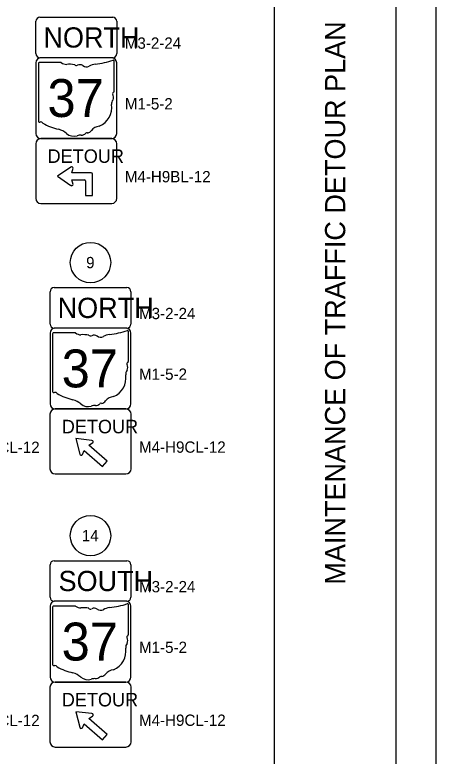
# Model space of a CAD drawing. Extents: x 0 to 680, y 0 to 440.
# Drawn here: x 575.8 to 680, y 150.5 to 333.9 of the extents above; entities that cross this region are included whole.
import ezdxf

# ---------------------------------------------------------------- set-up
doc = ezdxf.new("R2010")
doc.units = 0
for name, color, linetype in [('SH_Border', 7, 'Continuous'), ('SH_Cut_Line', 7, 'Continuous'), ('SH_Data', 7, 'Continuous'), ('SN_P_Signs', 7, 'Continuous'), ('SN_P_Text', 7, 'Continuous')]:
    doc.layers.add(name, color=color, linetype=linetype)

msp = doc.modelspace()

# ---------------------------------------------------------------- linework, layer by layer
at = {"layer": 'SH_Border'}
msp.add_line((640, 10), (640, 430), dxfattribs=at)
msp.add_lwpolyline([(30, 430), (670, 430), (670, 10), (30, 10)], close=True, dxfattribs=at)
at = {"layer": 'SH_Cut_Line'}
msp.add_lwpolyline([(0, 0), (680, 0), (680, 440), (0, 440)], close=True, dxfattribs=at)
at = {"layer": 'SN_P_Signs'}
for p, q in [((580.97, 324.26), (580.97, 332.26)), ((581.97, 333.26), (599.97, 333.26)), ((600.97, 332.26), (600.97, 324.26)), ((599.97, 323.26), (581.97, 323.26)), ((581.58, 321.81), (581.58, 307.58)), ((587.26, 322.06), (581.77, 322.06)), ((600.33, 314.97), (600.33, 322.41)), ((600.33, 314.97), (600.33, 314.97)), ((589.61, 296.18), (586.33, 293.93)), ((589.85, 294.81), (590.18, 295.94)), ((586.33, 293.93), (589.61, 291.69)), ((594.61, 294.81), (589.85, 294.81)), ((594.61, 294.81), (594.61, 294.81)), ((594.99, 289.17), (594.99, 294.44)), ((590.18, 291.93), (589.85, 293.06)), ((589.85, 293.06), (592.98, 293.06)), ((593.23, 292.81), (593.23, 289.17)), ((593.23, 289.17), (594.99, 289.17)), ((585.49, 266.39), (603.49, 266.39)), ((584.49, 257.39), (584.49, 265.39)), ((604.49, 265.39), (604.49, 257.39)), ((585.1, 254.95), (585.1, 240.72)), ((590.77, 255.2), (585.28, 255.2)), ((603.49, 256.39), (585.49, 256.39)), ((603.85, 248.11), (603.85, 255.55)), ((603.84, 248.11), (603.85, 248.11)), ((594.85, 228.61), (590.85, 229.08)), ((590.85, 229.08), (591.83, 225.23)), ((594.07, 227.42), (594.99, 227.99)), ((598.58, 223.47), (594.07, 227.42)), ((594.85, 228.61), (594.85, 228.61)), ((592.47, 225.12), (592.91, 226.1)), ((592.91, 226.1), (597.42, 222.15)), ((597.42, 222.15), (598.58, 223.47)), ((585.49, 198.86), (603.49, 198.86)), ((584.49, 189.86), (584.49, 197.86)), ((604.49, 197.86), (604.49, 189.86)), ((603.49, 188.86), (585.49, 188.86)), ((585.1, 187.41), (585.1, 173.18)), ((590.77, 187.66), (585.28, 187.66)), ((603.85, 180.57), (603.85, 188.01)), ((603.84, 180.57), (603.85, 180.57)), ((594.85, 161.07), (590.85, 161.54)), ((590.85, 161.54), (591.83, 157.7)), ((594.07, 159.89), (594.99, 160.45)), ((598.58, 155.93), (594.07, 159.89)), ((594.85, 161.07), (594.85, 161.07)), ((592.47, 157.58), (592.91, 158.56)), ((592.91, 158.57), (597.42, 154.61)), ((597.42, 154.61), (598.58, 155.93))]:
    msp.add_line(p, q, dxfattribs=at)
for points in [[(599.72, 323.26), (582.22, 323.26)], [(580.97, 322.01), (580.97, 304.51)], [(600.97, 304.51), (600.97, 322.01)], [(582.22, 303.26), (599.72, 303.26)], [(599.72, 303.26), (582.22, 303.26)], [(580.94, 301.97), (580.94, 288.48)], [(601.01, 288.48), (601.01, 301.97)], [(582.22, 287.2), (599.72, 287.2)], [(584.49, 255.14), (584.49, 237.64)], [(603.24, 256.39), (585.74, 256.39)], [(604.49, 237.64), (604.49, 255.14)], [(584.45, 235.11), (584.45, 221.62)], [(585.74, 236.39), (603.24, 236.39)], [(603.24, 236.39), (585.74, 236.39)], [(604.52, 221.62), (604.52, 235.11)], [(585.74, 220.34), (603.24, 220.34)], [(603.24, 188.86), (585.74, 188.86)], [(584.49, 187.61), (584.49, 170.11)], [(604.49, 170.11), (604.49, 187.61)], [(585.74, 168.86), (603.24, 168.86)], [(603.24, 168.86), (585.74, 168.86)], [(584.45, 167.57), (584.45, 154.08)], [(604.52, 154.08), (604.52, 167.57)], [(585.74, 152.8), (603.24, 152.8)]]:
    msp.add_lwpolyline(points, dxfattribs=at)
for centre in [(594.49, 272.59), (594.49, 205.06)]:
    msp.add_circle(centre, 5, dxfattribs=at)
for centre, radius, start, end in [((581.97, 332.26), 1, 90, 180), ((599.97, 332.26), 1, 0, 90), ((581.97, 324.26), 1, 180, 270), ((582.22, 322.01), 1.25, 90, 180), ((593.65, 341.46), 19.88, 275.8445, 288.9065), ((599.72, 322.01), 1.25, 0, 90), ((599.97, 324.26), 1, 270, 0), ((600.12, 322.44), 0.209, 351.8621, 97.738), ((581.8, 321.84), 0.217, 98.1301, 188.1301), ((588.57, 323.71), 2.11, 231.6195, 271.1119), ((589.26, 314.07), 7.56, 80.4867, 94.9883), ((590.98, 321.92), 0.608, 219.7921, 297.1024), ((591.87, 320.27), 1.26, 54.4667, 119.1411), ((593.5, 322.53), 1.52, 233.8562, 294.8282), ((596.19, 317.71), 4, 97.3462, 120.7689), ((600.28, 314.42), 0.323, 107.944, 210.337), ((598.23, 313.48), 1.94, 340.033, 23.6496), ((600.11, 314.94), 0.223, 289.6038, 7.7341), ((594.77, 310.91), 4.97, 292.3089, 8.9858), ((601.08, 311.85), 1.41, 136.8065, 186.9296), ((581.8, 307.55), 0.219, 171.9584, 258.3066), ((581.83, 309.01), 1.67, 267.339, 280.6039), ((582.17, 306.76), 0.603, 29.7484, 93.2717), ((589.79, 319.55), 14.36, 240.4129, 257.1985), ((596.86, 303.59), 2.72, 94.4031, 142.5768), ((582.22, 304.51), 1.25, 180, 270), ((585.51, 301.19), 4.49, 47.1842, 75.836), ((590.37, 306.69), 2.85, 230.7004, 286.2918), ((592.22, 305.63), 1.52, 268.777, 315.5493), ((593.6, 304.25), 0.428, 65.7517, 132.6484), ((593.41, 306.2), 1.61, 282.8732, 323.2771), ((599.72, 304.51), 1.25, 270, 0), ((582.22, 301.97), 1.28, 90, 180), ((592.01, 301.77), 2.34, 85.6951, 111.2099), ((599.72, 301.97), 1.28, 0, 90), ((589.85, 295.94), 0.335, 0.0017, 134.9999), ((594.61, 294.44), 0.376, 0, 90), ((589.85, 291.93), 0.335, 225.0001, 0.0017), ((592.98, 292.81), 0.25, 0, 90), ((582.22, 288.48), 1.28, 180, 270), ((599.72, 288.48), 1.28, 270, 0), ((585.48, 265.39), 1, 90, 180), ((603.48, 265.39), 1, 0, 90), ((585.48, 257.39), 1, 180, 270), ((603.48, 257.39), 1, 270, 0), ((585.74, 255.14), 1.25, 90, 180), ((585.31, 254.98), 0.217, 98.1301, 188.1301), ((592.08, 256.85), 2.11, 231.6195, 271.1119), ((599.7, 250.85), 4, 97.3462, 120.7689), ((597.17, 274.6), 19.88, 275.8445, 288.9065), ((603.24, 255.14), 1.25, 0, 90), ((603.64, 255.58), 0.209, 351.8621, 97.738), ((592.78, 247.21), 7.56, 80.4867, 94.9883), ((594.49, 255.06), 0.608, 219.7921, 297.1024), ((595.39, 253.41), 1.26, 54.4667, 119.1411), ((597.02, 255.67), 1.52, 233.8562, 294.8282), ((603.8, 247.56), 0.323, 107.944, 210.337), ((603.62, 248.08), 0.223, 289.6038, 7.7341), ((604.59, 244.99), 1.41, 136.8065, 186.9296), ((601.74, 246.62), 1.94, 340.033, 23.6496), ((598.28, 244.04), 4.97, 292.3089, 8.9858), ((585.31, 240.69), 0.219, 171.9584, 258.3066), ((585.35, 242.15), 1.67, 267.339, 280.6039), ((585.69, 239.9), 0.603, 29.7484, 93.2717), ((593.3, 252.69), 14.36, 240.4129, 257.1985), ((589.02, 234.33), 4.49, 47.1842, 75.836), ((596.93, 239.34), 1.61, 282.8732, 323.2771), ((600.38, 236.73), 2.72, 94.4031, 142.5768), ((585.74, 237.64), 1.25, 180, 270), ((593.88, 239.83), 2.85, 230.7004, 286.2918), ((595.53, 234.91), 2.34, 85.6951, 111.2099), ((595.73, 238.76), 1.52, 268.777, 315.5493), ((597.11, 237.39), 0.428, 65.7517, 132.6484), ((603.24, 237.64), 1.25, 270, 0), ((585.74, 235.11), 1.28, 90, 180), ((603.24, 235.11), 1.28, 0, 90), ((594.81, 228.27), 0.335, 301.5367, 83.3301), ((592.17, 225.26), 0.335, 183.7317, 335.9459), ((585.74, 221.62), 1.28, 180, 270), ((603.24, 221.62), 1.28, 270, 0), ((585.48, 197.86), 1, 90, 180), ((603.48, 197.86), 1, 0, 90), ((585.48, 189.86), 1, 180, 270), ((585.74, 187.61), 1.25, 90, 180), ((603.24, 187.61), 1.25, 0, 90), ((603.48, 189.86), 1, 270, 0), ((585.31, 187.44), 0.217, 98.1301, 188.1301), ((592.08, 189.31), 2.11, 231.6195, 271.1119), ((592.78, 179.67), 7.56, 80.4867, 94.9883), ((594.49, 187.52), 0.608, 219.7921, 297.1024), ((595.39, 185.87), 1.26, 54.4667, 119.1411), ((599.7, 183.31), 4, 97.3462, 120.7689), ((597.17, 207.06), 19.88, 275.8445, 288.9065), ((603.64, 188.04), 0.209, 351.8621, 97.738), ((597.02, 188.13), 1.52, 233.8562, 294.8282), ((603.8, 180.02), 0.323, 107.944, 210.337), ((601.74, 179.08), 1.94, 340.033, 23.6496), ((603.62, 180.54), 0.223, 289.6038, 7.7341), ((604.59, 177.45), 1.41, 136.8065, 186.9296), ((598.28, 176.51), 4.97, 292.3089, 8.9858), ((585.31, 173.15), 0.219, 171.9584, 258.3066), ((585.35, 174.61), 1.67, 267.339, 280.6039), ((585.69, 172.36), 0.603, 29.7484, 93.2717), ((593.3, 185.15), 14.36, 240.4129, 257.1985), ((589.02, 166.79), 4.49, 47.1842, 75.836), ((596.93, 171.8), 1.61, 282.8732, 323.2771), ((600.38, 169.19), 2.72, 94.4031, 142.5768), ((585.74, 167.57), 1.28, 90, 180), ((585.74, 170.11), 1.25, 180, 270), ((593.88, 172.29), 2.85, 230.7004, 286.2918), ((595.53, 167.37), 2.34, 85.6951, 111.2099), ((595.73, 171.23), 1.52, 268.777, 315.5493), ((597.11, 169.85), 0.428, 65.7517, 132.6484), ((603.24, 170.11), 1.25, 270, 0), ((603.24, 167.57), 1.28, 0, 90), ((594.81, 160.73), 0.335, 301.5367, 83.3301), ((592.17, 157.72), 0.335, 183.7317, 335.9459), ((585.74, 154.08), 1.28, 180, 270), ((603.24, 154.08), 1.28, 270, 0)]:
    msp.add_arc(centre, radius, start, end, dxfattribs=at)

# ---------------------------------------------------------------- texts
at = {"layer": 'SH_Data'}
msp.add_text('MAINTENANCE OF TRAFFIC DETOUR PLAN', height=5, rotation=90, dxfattribs=at).set_placement((657.5, 192.95))
at = {"layer": 'SN_P_Signs'}
for s, height, p in [('NORTH', 5, (582.84, 325.76)), ('37', 9.375, (583.83, 308.59)), ('DETOUR', 3.345, (583.87, 297.24)), ('9', 2.8, (593.4, 271.19)), ('NORTH', 5, (586.35, 258.89)), ('37', 9.375, (587.34, 241.73)), ('DETOUR', 3.345, (587.38, 230.37)), ('14', 2.8, (592.33, 203.66)), ('SOUTH', 5, (586.57, 191.36)), ('37', 9.375, (587.34, 174.19)), ('DETOUR', 3.345, (587.38, 162.84))]:
    msp.add_text(s, height=height, dxfattribs=at).set_placement(p)
at = {"layer": 'SN_P_Text'}
for s, p in [('M3-2-24', (602.97, 325.46)), ('M1-5-2', (602.97, 310.46)), ('M4-H9BL-12', (602.97, 292.43)), ('M3-2-24', (606.49, 258.6)), ('M1-5-2', (606.49, 243.6)), ('M4-H9RCL-12', (557.76, 225.51)), ('M4-H9CL-12', (606.49, 225.57)), ('M3-2-24', (606.49, 191.06)), ('M1-5-2', (606.49, 176.06)), ('M4-H9RCL-12', (557.76, 157.97)), ('M4-H9CL-12', (606.49, 158.03))]:
    msp.add_text(s, height=2.8, dxfattribs=at).set_placement(p)

doc.saveas('drawing.dxf')
